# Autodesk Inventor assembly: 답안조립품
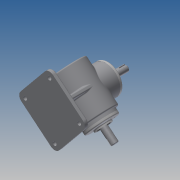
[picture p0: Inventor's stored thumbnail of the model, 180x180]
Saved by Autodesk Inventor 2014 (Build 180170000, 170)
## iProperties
Created: 2015-07
Part Number: 답안조립품
Document SubType Name: Assembly
Designer: SDA21
Author: SDA21
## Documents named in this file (14)
- C:\Users\SDA21\Desktop\450705V1022\답안조립품.iam
- C:\Users\SDA21\Desktop\450705V1022\본체.ipt
- C:\Users\SDA21\Desktop\450705V1022\450705V1022\메인 축.ipt
- 메인 축.ipt
- C:\Users\SDA21\Desktop\450705V1022\450705V1022\키 5x5.ipt
- C:\Users\SDA21\Desktop\450705V1022\450705V1022\서브 베벨기어.ipt
- C:\Users\SDA21\Desktop\450705V1022\450705V1022\메인 베벨기어.ipt
- C:\Users\SDA21\Desktop\450705V1022\450705V1022\커버.ipt
- C:\Users\SDA21\Desktop\450705V1022\450705V1022\베어링 6203.ipt
- C:\Users\SDA21\Desktop\450705V1022\450705V1022\서브 축.ipt
- 서브 축.ipt
- C:\Users\SDA21\Desktop\450705V1022\450705V1022\키 4x4.ipt
- C:\Users\SDA21\Desktop\450705V1022\450705V1022\오일실.ipt
- C:\Users\SDA21\Desktop\450705V1022\450705V1022\M4.ipt
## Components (8 placed, 1 different names)
1. M4:1 — 각도:7
2. M4:2 — 각도:5
3. M4:3 — 각도:6
4. M4:4 — 각도:8
5. M4:5 — 각도:10
6. M4:6 — 각도:9
7. M4:7 — 각도:12
8. M4:8 — 각도:11
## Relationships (8: Angle 8)
- 각도:5 [Angle]: M4:2
- 각도:6 [Angle]: M4:3
- 각도:7 [Angle]: M4:1
- 각도:8 [Angle]: M4:4
- 각도:9 [Angle]: M4:6
- 각도:10 [Angle]: M4:5
- 각도:11 [Angle]: M4:8
- 각도:12 [Angle]: M4:7
